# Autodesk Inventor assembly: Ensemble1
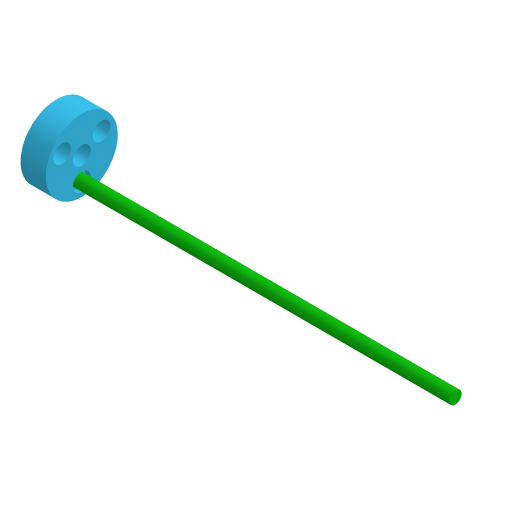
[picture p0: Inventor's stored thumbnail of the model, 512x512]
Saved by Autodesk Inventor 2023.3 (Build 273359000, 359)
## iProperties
Created: 2023-12
Part Number: Ensemble1
Document SubType Name: Assembly
Designer: Thier
Author: Thier
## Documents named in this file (3)
- C:\Travail\BTS TechCom\2-TechnoIndus\21-Meca\214-Systémes Industriels-SI\2141-Pièces Ecrites\21411-Cycle1\214112-TP02Eolienne\Ensemble1.iam
- C:\Travail\BTS TechCom\2-TechnoIndus\21-Meca\214-Systémes Industriels-SI\2141-Pièces Ecrites\21411-Cycle1\214112-TP02Eolienne\2141122-DossierTechniqueEolienne\21411223-Maquette numerique\214112232-CEB-Eolienne\Disque collecteur\terre.ipt
- C:\Travail\BTS TechCom\2-TechnoIndus\21-Meca\214-Systémes Industriels-SI\2141-Pièces Ecrites\21411-Cycle1\214112-TP02Eolienne\2141122-DossierTechniqueEolienne\21411223-Maquette numerique\214112232-CEB-Eolienne\Disque collecteur\Disque collecteur n.ipt
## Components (2 placed, 2 different names)
1. terre:1 — Logement:1
2. Disque collecteur n:1 — Logement:1
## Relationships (1: Insert 1)
- Logement:1 [Insert]: terre:1 ↔ Disque collecteur n:1
